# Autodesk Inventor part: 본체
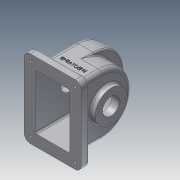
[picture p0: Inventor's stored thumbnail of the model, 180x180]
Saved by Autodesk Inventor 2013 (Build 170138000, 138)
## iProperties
Created: 2017-11
Part Number: 본체
Material: 알루미늄 6061
Document SubType Name: Modeling
Designer: Administrator
Density: 2.71 g/cm^3
Mass: 1079.55 g
Surface Area: 1182 cm^2
Volume: 398.359 cm^3
Author: Administrator
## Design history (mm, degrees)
sketch "스케치1"
  geometry: L1 (55, -75)-(-55, -75); L2 (-55, -75)-(-55, 75); L3 (-55, 75)-(55, 75); L4 (55, 75)-(55, -75); 3 further points
  constraints: 8 end point, 2 midpoint, 2 parallel, 1 horizontal, 1 horizontal alignment, 1 perpendicular, 1 vertical alignment
  dimensions: "d0" = 110 distance of L1.start L1.end; "d2" = 150 distance of L3.end L1.start
extrude "돌출1" new body sketch "스케치1" distance "d3" = 15; taper "d4" = 0 deg
node "작업 평면1"
sketch "스케치2"
  geometry: L1 (-73.548, 80)-(207.715, 80); L2 (-87.984, 144)-(207.715, 144); L3 (0, 0)-(150, 0) reference; L4 (17, 0)-(17, 80); L5 (133, 80)-(133, 0); L6 (17, 0)-(133, 0); A1 r 58 centre (75, 80) between (133, 80) and (17, 80); 3 further points
  constraints: 10 end point, 4 point on line, 3 perpendicular, 2 midpoint, 2 point on circle, 2 tangent, 1 centre point, 1 coincident, 1 horizontal, 1 parallel
  dimensions: "d6" = 80 distance from line of L1.start L3; "d7" = 144 distance from line of L2.start L3; "d8" = 58 radius of A1
extrude "돌출2" join sketch "스케치2" distance "d9" = 38; taper "d10" = 0 deg
sketch "스케치3"
  geometry: L1 (-133, 15)-(-17, 15) reference; L2 (-133, 15)-(-133, 80) reference; L3 (-17, 80)-(-17, 15) reference; L4 (-133, 15)-(-133, 57); L5 (-17, 57)-(-17, 15); L6 (-133, 15)-(-17, 15); L7 (-150, 0)-(0, 0) reference; A1 r 58 centre (-75, 80) between (-17, 80) and (-133, 80) reference; A2 r 58 centre (-75, 57) between (-17, 57) and (-133, 57); 2 further points
  constraints: 6 end point, 3 point on circle, 2 point on line, 2 tangent, 1 centre point, 1 collinear, 1 parallel, 1 perpendicular, 1 vertical alignment
  dimensions: "d11" = 58 radius of A2; "d12" = 57 distance from line of A2.centre L7
extrude "돌출3" join sketch "스케치3" distance "d13" = 38; taper "d14" = 0 deg
sketch "스케치4"
  geometry: L1 (-133, 57)-(-133, 15) reference; L2 (-17, 15)-(-133, 15) reference; L3 (-17, 15)-(-17, 57) reference; L4 (-162.838, 65)-(17.703, 65); L5 (-75, 115)-(-75, 15); L6 (-150, 0)-(0, 0) reference; C1 r 31 at (-75, 65); A1 r 58 centre (-75, 57) between (-17, 57) and (-133, 57) reference; 1 further point
  constraints: 4 end point, 2 midpoint, 1 centre point, 1 perpendicular, 1 point on circle
  dimensions: "d15" = 65 distance from line of L4.start L6; "d16" = 62 diameter of C1
extrude "돌출4" join sketch "스케치4" distance "d17" = 10; taper "d18" = 0 deg
sketch "스케치5"
  geometry: C1 r 31 at (75, 65) reference; C2 r 37.5 at (75, 65); 1 further point
  constraints: 1 centre point, 1 coincident
  dimensions: "d19" = 75 diameter of C2
extrude "돌출5" join sketch "스케치5" distance "d21" = 9; taper "d22" = 0 deg
node "작업 평면2"
sketch "스케치6"
  geometry: L1 (133, 15)-(150, 15) reference; L2 (150, 15)-(150, 0) reference; L3 (150, 0)-(0, 0) reference; L4 (0, 0)-(0, 15) reference; L5 (0, 15)-(17, 15) reference; L6 (17, 15)-(17, 80) reference; L7 (133, 80)-(133, 15) reference; L8 (22, 80)-(22, 0); L9 (128, 80)-(128, 0); L10 (128, 0)-(22, 0); A1 r 58 centre (75, 80) between (133, 80) and (17, 80) reference; A2 r 53 centre (75, 80) between (128, 80) and (22, 80); 1 further point
  constraints: 6 end point, 2 perpendicular, 2 point on circle, 2 point on line, 2 tangent, 1 centre point, 1 coincident, 1 collinear
  dimensions: "d24" = 106 diameter of A2
extrude "돌출6" cut sketch "스케치6" distance "d26" = 28; taper "d27" = 0 deg
node "작업 평면3"
sketch "스케치7"
  geometry: L1 (-17, 15)-(0, 15) reference; L2 (0, 15)-(0, 0) reference; L3 (0, 0)-(-150, 0) reference; L4 (-150, 0)-(-150, 15) reference; L5 (-150, 15)-(-133, 15) reference; L6 (-133, 15)-(-133, 57) reference; L7 (-17, 57)-(-17, 15) reference; L8 (-128, 57)-(-128, 0); L9 (-22, 57)-(-22, 0); L10 (-22, 0)-(-128, 0); A1 r 58 centre (-75, 57) between (-17, 57) and (-133, 57) reference; A2 r 53 centre (-75, 57) between (-22, 57) and (-128, 57); 1 further point
  constraints: 6 end point, 2 perpendicular, 2 point on circle, 2 point on line, 2 tangent, 1 centre point, 1 coincident, 1 collinear
  dimensions: "d30" = 106 diameter of A2
extrude "돌출7" cut sketch "스케치7" distance "d32" = 38.25; taper "d33" = 0 deg
hole "구멍1" diameter "d36" = 32; stored, may be unused: countersink angle "d40" = 90 deg, drill point angle "d42" = 118 deg; dims "d34" = 10, "d35" = 10, "d37" = 6, "d38" = 4, "d39" = 2, "d41" = 8
sketch "스케치8"
  geometry: L1 (-75, -50)-(75, -50) reference; L2 (75, -50)-(75, -65) reference; L3 (75, -65)-(-75, -65) reference; L4 (-75, -65)-(-75, -50) reference; C1 r 16 at (0, 0) reference; C2 r 37.5 at (0, 0) reference; A1 r 29 centre (0, 0) between (0, 29) and (-29, 0); 3 further points
  constraints: 4 point on circle, 1 centre point, 1 coincident
  dimensions: "d43" = 58 diameter of A1
hole "구멍2" sketch "스케치8" at (0, 29), (-29, 0), (0, -29), (29, 0) diameter "d45" = 2.459; stored, may be unused: countersink angle "d49" = 90 deg, drill point angle "d51" = 118 deg; dims "d46" = 6, "d47" = 4, "d48" = 2, "d50" = 8
sketch "스케치9"
  geometry: L1 (-75, -50)-(75, -50) reference; L2 (75, -50)-(75, -65) reference; L3 (75, -65)-(-75, -65) reference; L4 (-75, -65)-(-75, -50) reference; C1 r 16 at (0, 0) reference; C2 r 31 at (0, 0) reference; A1 r 26 centre (0, 0) between (0, 26) and (-26, 0); 3 further points
  constraints: 4 point on circle, 1 centre point, 1 coincident
  dimensions: "d52" = 52 diameter of A1
hole "구멍3" sketch "스케치9" at (0, 26), (-26, 0), (0, -26), (26, 0) diameter "d54" = 2.459; stored, may be unused: countersink angle "d58" = 90 deg, drill point angle "d60" = 118 deg; dims "d55" = 6, "d56" = 4, "d57" = 2, "d59" = 8
node "작업 평면4"
sketch "스케치10"
  geometry: L1 (38, -58)-(38, 58) reference; C1 r 6 at (19, 0); 1 further point
  constraints: 1 centre point, 1 horizontal alignment
  dimensions: "d62" = 12 diameter of C1; "d64" = 19 distance from line of C1.centre L1
extrude "돌출8" join sketch "스케치10" distance "d65" = 7; taper "d66" = 0 deg
hole "구멍4" diameter "d69" = 4.134; stored, may be unused: countersink angle "d73" = 90 deg, drill point angle "d75" = 118 deg; dims "d70" = 6, "d71" = 4, "d72" = 2, "d74" = 8, "d76" = 10, "d77" = 10
fillet "모깎기1" dims "d78" = 12
hole "구멍5" diameter "d81" = 5; stored, may be unused: countersink angle "d85" = 90 deg, drill point angle "d87" = 118 deg; dims "d79" = 10, "d80" = 10, "d82" = 6, "d83" = 12, "d84" = 5, "d86" = 8
fillet "모깎기2" dims "d88" = 8
fillet "모깎기3" dims "d89" = 3
chamfer "모따기1" distance "d90" = 1; stored, may be unused: second distance "d91" = 2, angle "d92" = 45 deg
sketch "스케치11"
  geometry: L1 (4.455, 34.95)-(55.545, 34.95); L2 (55.545, 34.95)-(55.545, 9.05); L3 (55.545, 9.05)-(4.455, 9.05); L4 (4.455, 9.05)-(4.455, 34.95); L5 (73, -18)-(-13, -18) reference; L6 (-8, 62)-(-8, 0) reference; 3 further points
  constraints: 2 midpoint, 2 other
  dimensions: "d93" = 40 distance from line of point (4.455, 22) L5; "d94" = 38 distance from line of point (30, 34.95) L6
feature "엠보싱1" sketch "스케치11" dims "d0" = 110, "d2" = 150, "d95" = 0.5, "d96" = 0
node "솔리드1"
mirror "대칭1"
mirror "대칭2"
node "투영된 루프1"
node "투영된 루프2"
node "투영된 루프3"
node "절단 모서리 투영1"
node "절단 모서리 투영2"
node "절단 모서리 투영3"
node "절단 모서리 투영4"
other parameters: "d5" = -55, "d23" = 5, "d29" = -5, "d61" = 144
